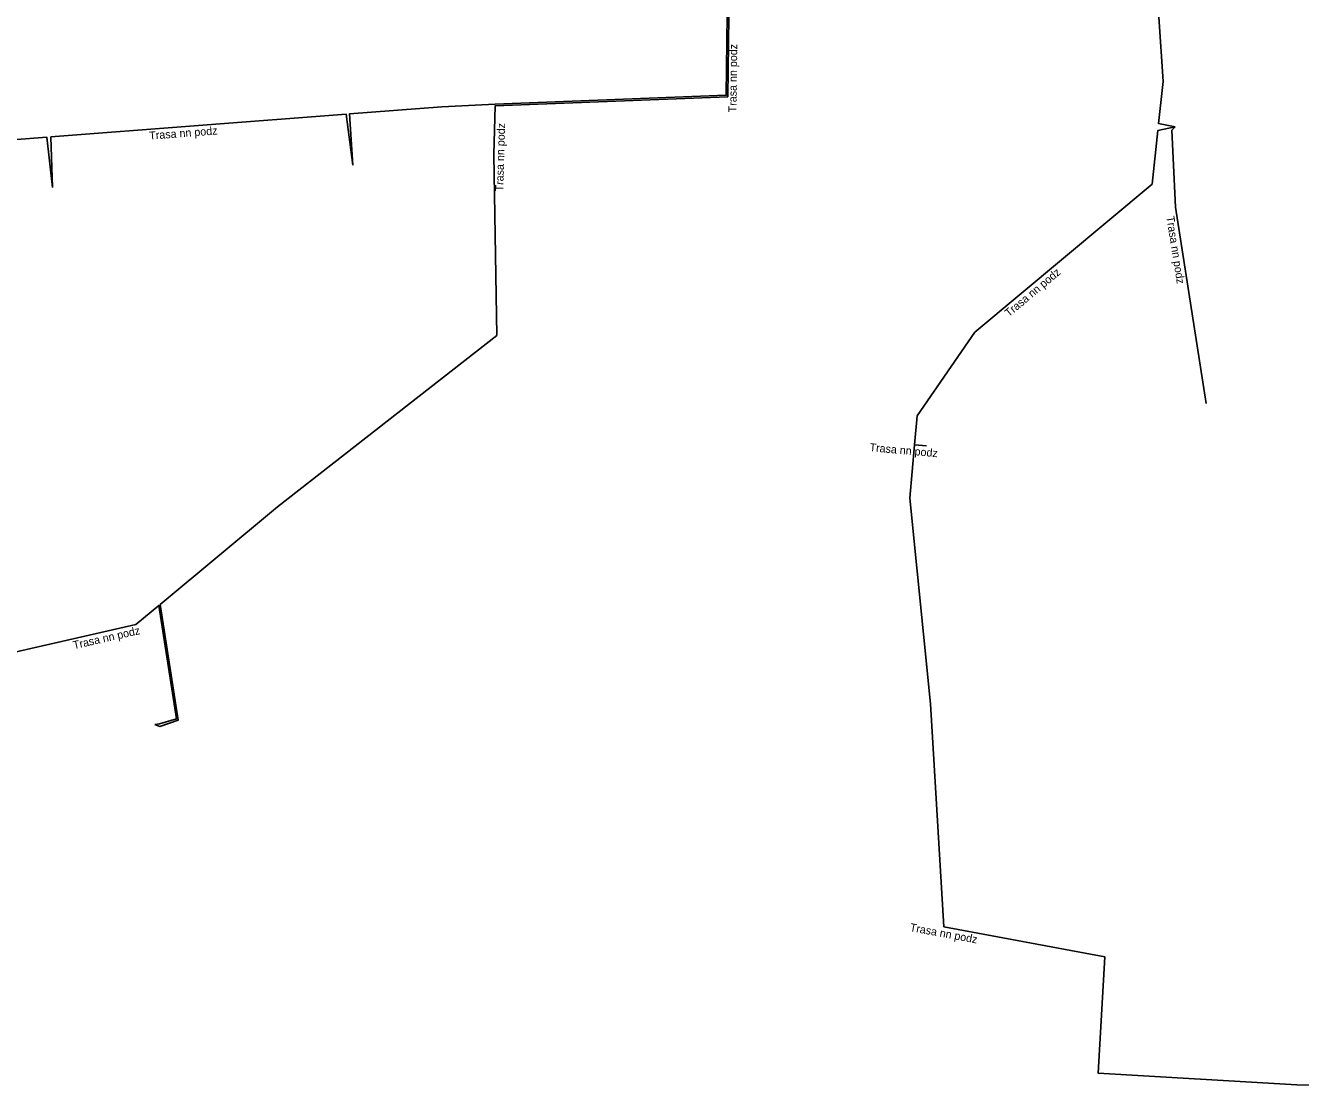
# Model space of a CAD drawing. Extents: x -873583 to -872966, y -1012951 to -1012536.
# Drawn here: x -873138.5 to -873058.9, y -1012748.5 to -1012682.3 of the extents above; entities that cross this region are included whole.
import ezdxf

# ---------------------------------------------------------------- set-up
doc = ezdxf.new("R2010")
doc.units = 0
doc.layers.add('Popiskový text - Ostatní atributy Trasy', color=7, linetype='Continuous')
doc.layers.add('Spojnice NN', color=7, linetype='Continuous')

msp = doc.modelspace()

# ---------------------------------------------------------------- linework, layer by layer
at = {"layer": 'Spojnice NN'}
for points in [[(-873130.472, -1012725.94), (-873130.159, -1012726.063), (-873128.997, -1012725.666), (-873130.141, -1012718.456), (-873122.81, -1012712.344), (-873109.109, -1012701.646), (-873109.288, -1012690.336), (-873109.203, -1012687.296), (-873094.672, -1012686.744), (-873094.438, -1012668.249), (-873094.501, -1012657.584), (-873096.261, -1012657.678), (-873096.543, -1012657.653)], [(-873096.543, -1012657.653), (-873096.22, -1012657.827), (-873094.6, -1012657.692), (-873094.538, -1012668.249), (-873094.771, -1012686.648), (-873109.207, -1012687.196), (-873112.537, -1012687.362), (-873118.302, -1012687.798), (-873118.092, -1012691.007)], [(-873066.607, -1012671.488), (-873067.89, -1012671.693), (-873067.909, -1012672.327), (-873068.215, -1012677.962), (-873067.749, -1012681.739), (-873067.486, -1012685.785), (-873067.766, -1012688.418), (-873066.733, -1012688.611)], [(-873118.092, -1012691.007), (-873118.516, -1012687.819), (-873136.952, -1012689.246), (-873136.852, -1012692.407)], [(-873066.733, -1012688.611), (-873067.81, -1012688.839), (-873068.166, -1012692.194), (-873079.243, -1012701.444), (-873082.854, -1012706.673), (-873083.015, -1012708.473)], [(-873066.733, -1012688.611), (-873066.932, -1012688.832), (-873066.718, -1012693.644), (-873064.784, -1012705.891)], [(-873136.852, -1012692.407), (-873137.204, -1012689.266), (-873147.951, -1012690.095), (-873178.056, -1012692.383), (-873185.094, -1012692.854), (-873185.016, -1012696.143)], [(-873083.015, -1012708.473), (-873083.313, -1012711.801), (-873082.006, -1012724.663), (-873081.176, -1012738.58), (-873071.115, -1012740.458), (-873071.533, -1012747.72), (-873059.139, -1012748.456), (-873056.946, -1012748.489), (-873056.702, -1012748.432)], [(-873083.015, -1012708.473), (-873082.27, -1012708.54)], [(-873141.792, -1012723.87), (-873142.006, -1012722.16), (-873140.683, -1012721.762), (-873131.65, -1012719.695), (-873130.224, -1012718.506), (-873129.109, -1012725.598), (-873130.173, -1012725.907), (-873130.472, -1012725.94)]]:
    msp.add_lwpolyline(points, dxfattribs=at)

# ---------------------------------------------------------------- texts
at = {"layer": 'Popiskový text - Ostatní atributy Trasy'}
for rotation, p in [(89.27289, (-873094.135, -1012687.718)), (4.42746, (-873130.795, -1012689.421)), (88.40297, (-873108.702, -1012692.657)), (278.97305, (-873067.283, -1012694.234)), (39.86479, (-873077.119, -1012700.516)), (354.8437, (-873085.836, -1012708.871)), (12.88744, (-873135.513, -1012721.246)), (349.43141, (-873083.33, -1012738.84))]:
    msp.add_text('Trasa nn podz', height=0.5, rotation=rotation, dxfattribs=at).set_placement(p)

doc.saveas('drawing.dxf')
